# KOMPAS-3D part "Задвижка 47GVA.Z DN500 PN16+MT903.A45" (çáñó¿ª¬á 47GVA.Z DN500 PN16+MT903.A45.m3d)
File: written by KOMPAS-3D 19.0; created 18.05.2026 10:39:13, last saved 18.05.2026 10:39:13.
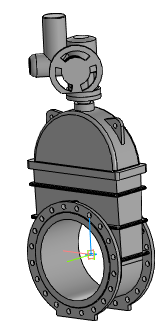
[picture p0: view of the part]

Document properties: Автор: Энергия; Полное имя файла: ..\Задвижка 47GVA.Z DN350_DN1200+MT903.A\Задвижка 47GVA.Z DN500 PN16+MT903.A45.a3d

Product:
- Part/product: Задвижка 47GVA.Z DN500 PN16+MT903.A45
    Масса: 1150.21
  - Body: Электропривод МТ903.А45 без блока управления
      Масса: 175.721
  - Body: Задвижка 47GVA.Z DN500 PN16 без исполнит. мех.
      Масса: 974.485

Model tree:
1. Операция без истории:1
2. Операция без истории:2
